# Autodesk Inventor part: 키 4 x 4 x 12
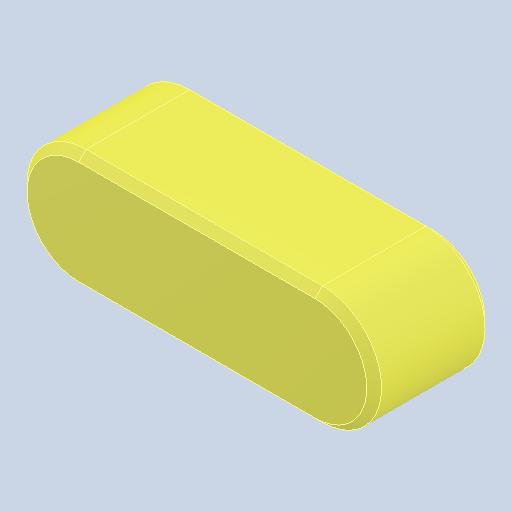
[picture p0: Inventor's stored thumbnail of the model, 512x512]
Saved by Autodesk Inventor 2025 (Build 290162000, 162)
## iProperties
Created: 2024-07
Part Number: 키 4 x 4 x 12
Material: 강철, 연강
Description: 키 및 해당 키홈
Document SubType Name: Modeling
Designer: Administrator
Density: 7.85 g/cm^3
Appearance: 기본값
Author: jhkim
Sending System: Autodesk Inventor 2025
Preprocessor: ST-DEVELOPER v20
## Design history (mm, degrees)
feature "Solid1"
node "솔리드1"
